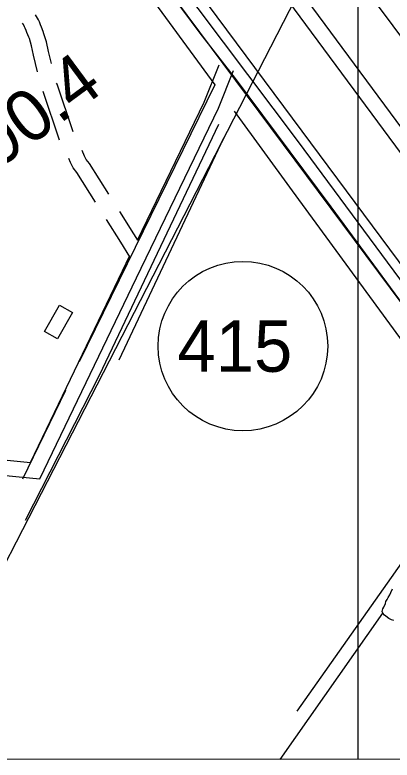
# Model space of a CAD drawing. Extents: x 3263578 to 3301413, y 764927 to 798602.
# Drawn here: x 3285407 to 3286141, y 775829 to 777281 of the extents above; entities that cross this region are included whole.
import ezdxf

# ---------------------------------------------------------------- set-up
doc = ezdxf.new("R2010")
doc.units = 0
for name, color, linetype in [('V-BLDG-OTLN', 7, 'Continuous'), ('V-DTCH-CNTR', 7, 'Continuous'), ('V-GRID-FRAM', 7, 'Continuous'), ('V-GRID-MAJR', 7, 'Continuous'), ('V-LEVE-TOET', 7, 'Continuous'), ('V-ROAD-CNTR', 7, 'Continuous'), ('V-ROAD-IDEN', 7, 'Continuous'), ('V-SURV-IDEN', 7, 'Continuous'), ('V-SURV-LINE', 7, 'Continuous'), ('V-TOPO-BNDY', 7, 'Continuous'), ('V-TOPO-SHOR', 7, 'Continuous')]:
    doc.layers.add(name, color=color, linetype=linetype)

msp = doc.modelspace()

# ---------------------------------------------------------------- linework, layer by layer
at = {"layer": 'V-BLDG-OTLN'}
msp.add_lwpolyline([(3285465.1, 776664), (3285494.5, 776715.6), (3285519.8, 776701.2), (3285490.4, 776649.6)], close=True, dxfattribs=at)
at = {"layer": 'V-DTCH-CNTR'}
msp.add_line((3285813.5, 777040.9), (3285609.7, 776608.6), dxfattribs=at)
msp.add_lwpolyline([(3286319.7, 776443), (3286206.5, 776280.1), (3285955.8, 775924.5)], dxfattribs=at)
at = {"layer": 'V-GRID-FRAM'}
msp.add_lwpolyline([(3267734.9, 794015.5), (3299171.2, 794017.8), (3299180.4, 775831.7), (3267728.3, 775829.4), (3267734.9, 794015.5)], dxfattribs=at)
at = {"layer": 'V-GRID-MAJR'}
msp.add_spline([(3286075.4, 775830.8), (3286074.5, 781889.4), (3286073.6, 787951.5), (3286072.7, 794013.5), (3286072.7, 794016.9)], degree=3, dxfattribs=at)
at = {"layer": 'V-LEVE-TOET'}
for points in [[(3284126.3, 779529.1), (3284162.9, 779488.4), (3284218.5, 779416.3), (3284353, 779234.8), (3284501.4, 779037.8), (3284646, 778841.6), (3284765.5, 778673.7), (3284949.2, 778430), (3285219, 778068), (3285459.2, 777737.5), (3285691.2, 777424.3), (3285965.8, 777054.1), (3286222.6, 776708.5), (3286385.9, 776484.8), (3286571.9, 776233.4), (3286758.9, 775979.6), (3286871.1, 775830.8)], [(3287161.8, 775830.9), (3287131.1, 775890.3), (3287046.7, 776024.8), (3286938.6, 776189.3), (3286930.1, 776200.3), (3286881.3, 776262.8), (3286620.6, 776615.7), (3286369.9, 776955.7), (3286114.9, 777297.8), (3285934.2, 777538), (3285840, 777634.2), (3285749.6, 777751.3), (3285729.7, 777777.6), (3285706.2, 777802.7), (3285684.1, 777829), (3285660.6, 777857.1), (3285622.8, 777919.3), (3285398.6, 778209.6)]]:
    msp.add_lwpolyline(points, dxfattribs=at)
at = {"layer": 'V-ROAD-CNTR'}
msp.add_line((3285494.5, 777036.8), (3285462.5, 777131.6), dxfattribs=at)
for points in [[(3286817.5, 775833.6), (3286161.1, 776718.1), (3285511.5, 777590.9), (3285032.8, 778237.4), (3284479.5, 778985.2), (3284180.8, 779387.8)], [(3285403.5, 777739.3), (3285523.3, 777574.5), (3285767.5, 777245.3), (3285836.1, 777156.8)], [(3285478.6, 777186.1), (3285473.1, 777209.3), (3285468.9, 777228.4), (3285464, 777244.1), (3285462.5, 777248.3), (3285459, 777257.1), (3285457.4, 777261.5), (3285455.1, 777267), (3285453.1, 777271), (3285449.6, 777277.8), (3285447.7, 777280.7)], [(3285451.5, 777169.9), (3285443.9, 777202.6), (3285439.9, 777220.7), (3285435.5, 777234.6), (3285434.4, 777237.7), (3285430.9, 777246.6), (3285429.4, 777250.6), (3285427.7, 777254.7), (3285426.3, 777257.7), (3285423.9, 777262.3), (3285422, 777264.9)], [(3285382.9, 776384.6), (3285455.8, 776376.9), (3285643.8, 776769), (3285803.3, 777099), (3285832.5, 777172.8)], [(3285645.9, 776842.1), (3285775.8, 777111), (3285804.6, 777183.8)], [(3285520.8, 777052.8), (3285489.4, 777145.9), (3285488.6, 777147.5)], [(3285836.1, 777156.8), (3286022.5, 776906.7), (3286246.2, 776602.6), (3286504.3, 776256.5), (3286568.2, 776171)], [(3285590, 776931.7), (3285552.4, 776991.1), (3285546.2, 776999.1), (3285543, 777005.8), (3285538.3, 777017)], [(3285564.4, 776916), (3285527.8, 776973.9), (3285520.6, 776983.2), (3285515.6, 776993.5), (3285512.4, 777001.2)], [(3285646.5, 776842), (3285639.1, 776854.2), (3285611.4, 776897.9)], [(3285631.1, 776809.9), (3285613.6, 776838.4), (3285585.8, 776882.2)], [(3285386.1, 776414.4), (3285437.9, 776408.9), (3285616.8, 776782), (3285630.6, 776810.6)]]:
    msp.add_lwpolyline(points, dxfattribs=at)
at = {"layer": 'V-ROAD-IDEN'}
msp.add_circle((3285851.1, 776635.8), 165, dxfattribs=at)
at = {"layer": 'V-SURV-LINE'}
for points in [[(3285916.7, 777390.2), (3287068.6, 775830.8)], [(3287031.3, 775830.8), (3285892.6, 777372.4)]]:
    msp.add_lwpolyline(points, dxfattribs=at)
at = {"layer": 'V-TOPO-BNDY'}
msp.add_lwpolyline([(3287656.3, 780630.4), (3285191.7, 775830.7)], dxfattribs=at)
at = {"layer": 'V-TOPO-SHOR'}
for p, q in [((3285422.6, 776377.3), (3285506.5, 776549.8)), ((3285923.3, 775830.9), (3286123.6, 776115.5))]:
    msp.add_line(p, q, dxfattribs=at)
for points in [[(3286853, 775830.9), (3286438.5, 776389.2), (3286318.7, 776547.3), (3285959.4, 777033.7), (3285715, 777359.6), (3285441.9, 777723.8)], [(3285388.6, 777328.8), (3285419.3, 777525.2), (3285428.5, 777589.6), (3285440.8, 777604.9), (3285453.1, 777614.1), (3285796.6, 777144.7), (3285532.7, 776604.8)], [(3286306.8, 776446.7), (3285947.4, 776937.9), (3285834.8, 777093.6)], [(3285803.7, 777067.3), (3285571.2, 776578.5), (3285427.4, 776295.8)], [(3286144.9, 776101.5), (3286140.1, 776102.7), (3286135.2, 776105.1), (3286129.2, 776109.5), (3286126.4, 776111.9), (3286123.6, 776115.5), (3286122.3, 776118.7), (3286123.5, 776123.9), (3286125.1, 776127.2), (3286128.3, 776134.4), (3286129.5, 776138), (3286131.9, 776142.5), (3286133.9, 776146.1), (3286136.7, 776151.3), (3286138.7, 776156.1), (3286141.9, 776163)]]:
    msp.add_lwpolyline(points, dxfattribs=at)

# ---------------------------------------------------------------- texts
at = {"layer": 'V-ROAD-IDEN'}
msp.add_text('415', height=100, rotation=359.9292, dxfattribs=at).set_placement((3285723.9, 776585.9))
at = {"layer": 'V-SURV-IDEN'}
msp.add_text('2663+90.4', height=100, rotation=36.4442, dxfattribs=at).set_placement((3285071.8, 776755.4))

doc.saveas('drawing.dxf')
